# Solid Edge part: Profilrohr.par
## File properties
Username: ahadarics
Dokumentum tartalom típus: 0
Author: ahadarics
Last saved by: ahadarics
Revision: 87
Sűrűség: 0,000 kg/m^3
Pontosság: 0,990
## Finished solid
Body 1: solid body, 6 faces, 6 edges, 0 vertices.
  Faces by surface: cone 2, cylinder 2, plane 2
  Edges by curve: circle 6
Bounding box of the edges (mm): 21.270 x 21.270 x 532.000, from (-10.635, -10.635, -511) to (10.635, 10.635, 21).
Cylindrical faces by radius (mm): R10 x1, R10.635 x1
Conical faces (half-angle, radius in mm at the cone's reference point): 15 deg R10.067 x2
Planar faces by outward normal: +z 1, -z 1
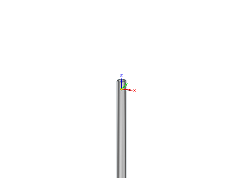
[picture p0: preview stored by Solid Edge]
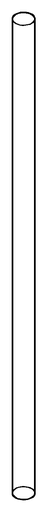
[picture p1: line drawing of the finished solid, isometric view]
